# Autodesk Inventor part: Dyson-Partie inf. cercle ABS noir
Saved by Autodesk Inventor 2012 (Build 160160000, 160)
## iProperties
Created: 2012-11
Part Number: Dyson-Partie inf. cercle ABS noir
Material: Default
Document SubType Name: Modeling
Designer: Administrateur
Density: 1 g/cm^3
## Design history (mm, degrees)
node "Dyson-Partie inf. cercle ABS noir1"
node "Dyson-Partie inf. cercle ABS noir"
node "Base1"
